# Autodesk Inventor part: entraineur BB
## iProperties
Created: 2011-09
Part Number: entraineur BB
Document SubType Name: Modeling
Designer: A
Manufacturer: Standard
Standards Organization: Custom
Author: A
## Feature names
1. Extrusion1
2. Extrusion2
3. Perçage1 [Hole]
4. Perçage2 [Hole]
5. Perçage3 [Hole]
6. Extrusion3
